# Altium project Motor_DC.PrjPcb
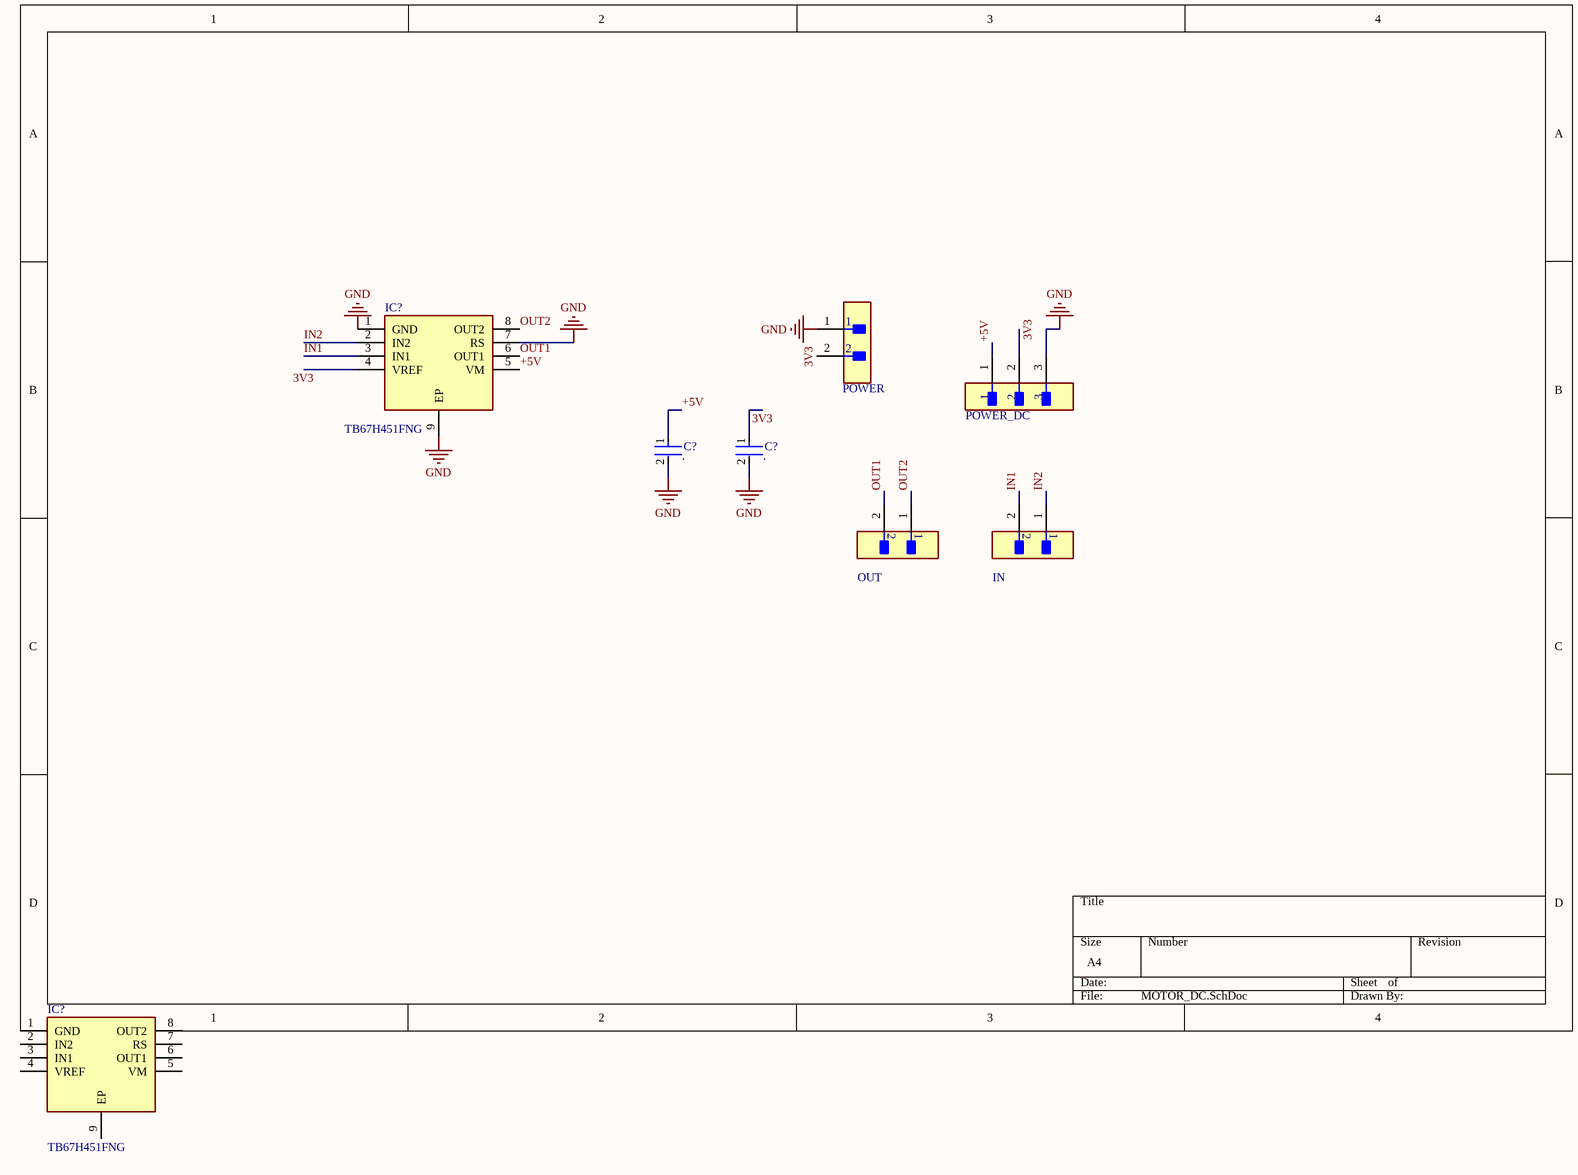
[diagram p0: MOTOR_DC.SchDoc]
1 sheet, 8 parts. Net scope: global (net labels, ports and power ports of the same name join across sheets).
Board file: MOTOR_DC.PcbDoc

## Sheet MOTOR_DC.SchDoc
size A4; SheetNumber: 1; SheetTotal: 1

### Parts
(Parts that share a designator on the sheet are numbered #1, #2 ... from top to bottom, then left to right.)
C?#1  .  [FP-C1206C-EB-MFG]
C?#2  .  [FP-C1206C-EB-MFG]
IC?#1  TB67H451FNG  [SOIC127P600X170-9N]
IC?#2  TB67H451FNG  [SOIC127P600X170-9N]
IN  M20-9990246  [FP-M20-9990246-MFG]  (value not drawn)
OUT  M20-9990246  [FP-M20-9990246-MFG]  (value not drawn)
POWER  M20-9990246  [FP-M20-9990246-MFG]  (value not drawn)
POWER_DC  (no value)  [FP-PR20203VBNN-MFG]

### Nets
GND: C?#1.2 C?#2.2 IC?#1.1(GND) IC?#1.7(RS) IC?#1.9(EP) POWER.1 POWER_DC.3
3V3: C?#2.1 IC?#1.4(VREF) POWER.2 POWER_DC.2
+5V: C?#1.1 IC?#1.5(VM) POWER_DC.1
IN1: IC?#1.3(IN1) IN.2
IN2: IC?#1.2(IN2) IN.1
OUT1: IC?#1.6(OUT1) OUT.2
OUT2: IC?#1.8(OUT2) OUT.1

Not connected (* = marked no-connect by the designer): IC?#2 1(GND) 2(IN2) 3(IN1) 4(VREF) 5(VM) 6(OUT1) 7(RS) 8(OUT2) 9(EP)

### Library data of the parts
C?#1 C?#2 = CMP-03020-023751-1: C1206 100 pF X8R 10.00% 50 V; Manufacturer: KEMET; Manufacturer Part Number: C1206C101K5HACTU; Capacitance: 100 pF; Temperature Coefficient: 15%; Voltage Rating: 50 V; Tolerance: 0.1; Automotive Grade: Grade 0; Value: 100 pF; Material: Ceramic
IC?#1 IC?#2 = TB67H451FNG: Integrated Circuit; Manufacturer_Name: Toshiba
IN OUT POWER = CMP-15831-000009-1: CONN HEADER VERT 2POS 2.54MM; Manufacturer: Harwin; Conn Gender: Male; Conn Orientation: Vertical; Number Of Contacts: 2; Current Rating: 3A
POWER_DC = CMP-77940-000002-1: CONN HEADER VERT 3POS 2.54MM; Manufacturer Part Number: PR20203VBNN; Manufacturer: Metz Connect; Conn Orientation: Straight; Current Rating: 3A; Number Of Contacts: 3; Conn Gender: Male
